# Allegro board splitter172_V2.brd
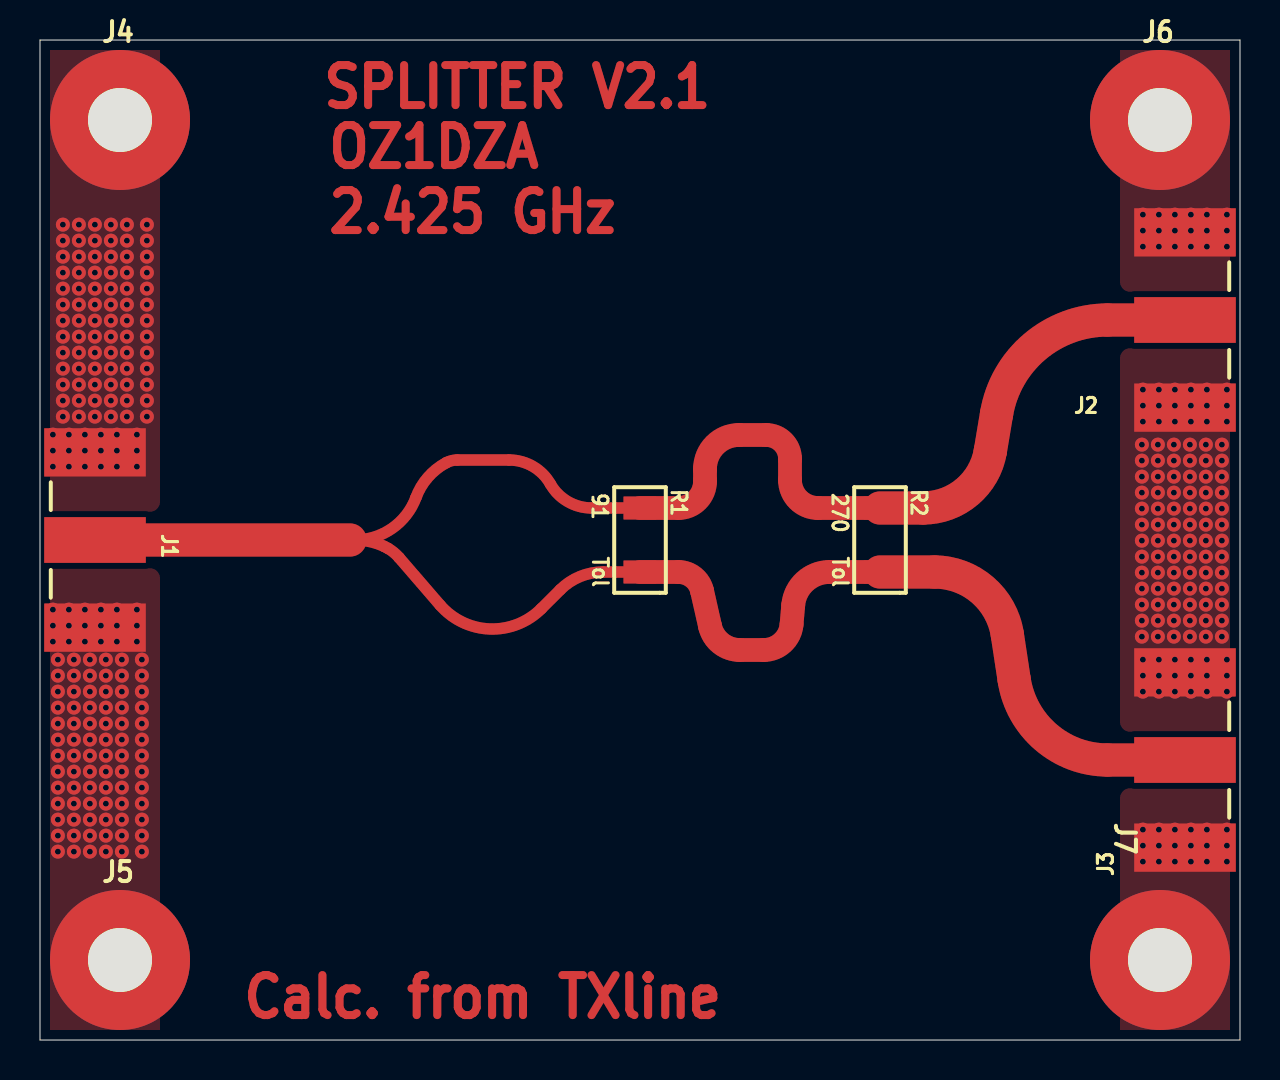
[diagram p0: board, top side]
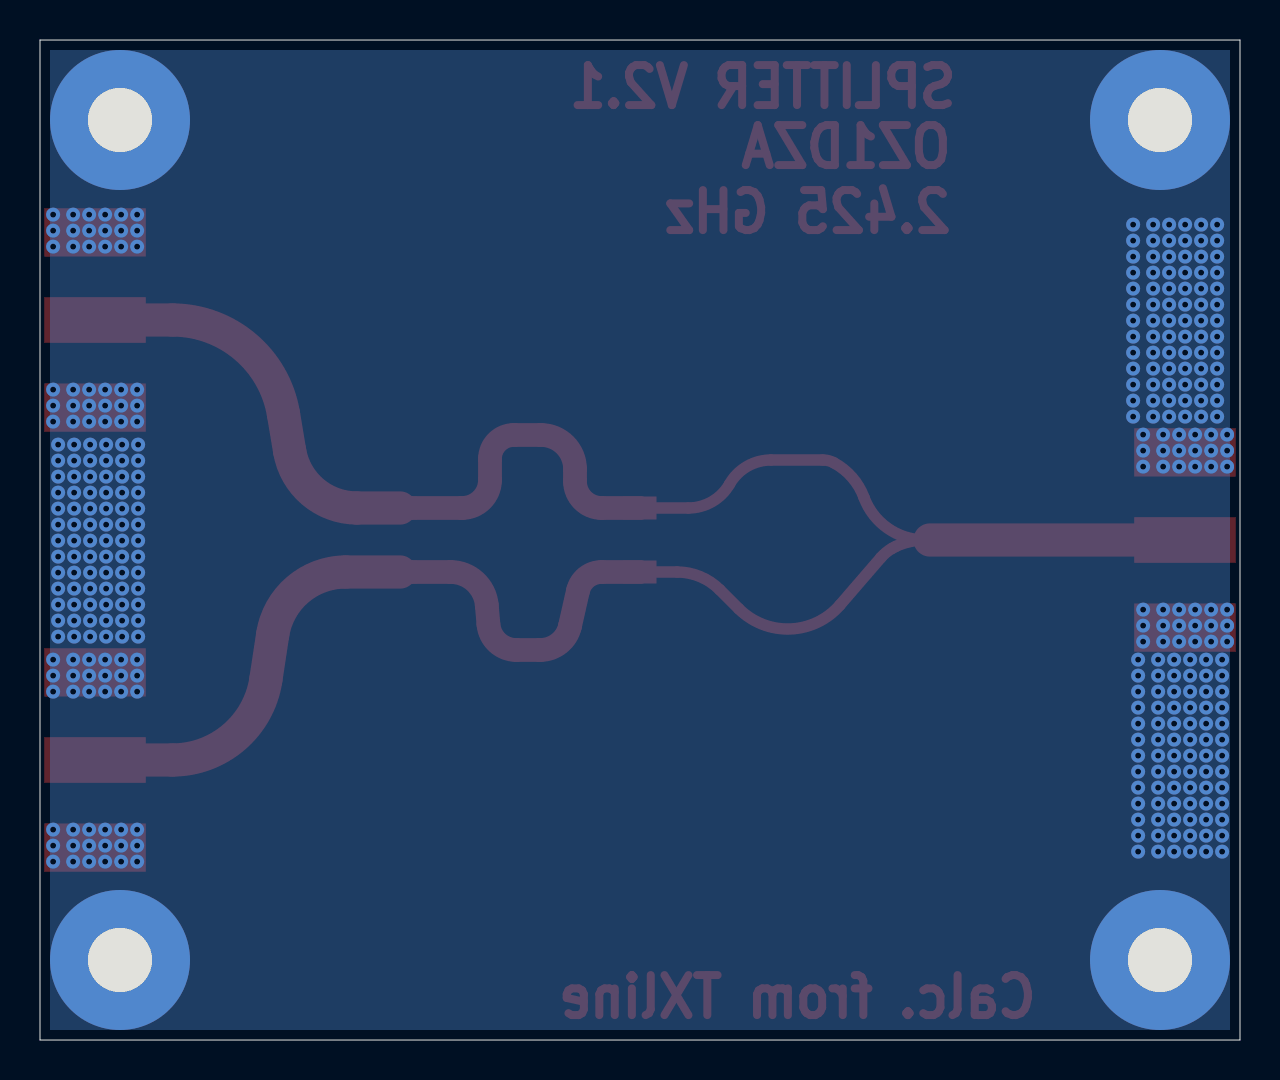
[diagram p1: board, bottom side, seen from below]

Outline 60 x 50 mm; copper layers: TOP, BOTTOM. Coordinates in mm from the lower left corner of the outline.
Outline path: 0,50 0,0 60,0 60,50 0,50

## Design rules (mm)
constraint set DEFAULT: min track width 0.3

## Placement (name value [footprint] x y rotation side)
J1  142-0701-801  [142-0701-851]  6.94 22.81 270 top
J2  142-0701-801  [142-0701-851]  53.06 38.19 90 top
J3  142-0701-801  [142-0701-851]  53.06 16.19 90 top
J4  -  [CON_C700H320]  4 46 0 top
J5  -  [CON_C700H320]  4 4 0 top
J6  -  [CON_C700H320]  56 46 0 top
J7  -  [CON_C700H320]  56 4 0 top
NOREF  -  []  0 50 0 top
NOREF#2  -  []  0 50 0 top
NOREF#3  -  []  60 0 90 top
R1  91  [R1206]  30 25 270 top
R2  270  [R1206]  42 25 270 top

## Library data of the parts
J1-J3 = 142-0701-801
J4-J7 = CON1
R1 = RC0603FR-0791RL: Tolerance: Tol
R2 = RMCF0603FT270R: Tolerance: Tol

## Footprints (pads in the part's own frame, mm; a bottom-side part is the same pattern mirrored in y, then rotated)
142-0701-851
  rect 2.413x5.08 smd: 1(-6.572,-4.19) 3(2.191,-4.19)
  rect 2.286x5.08 smd: 2(-2.191,-4.19)
CON_C700H320
  round 7 hole 3.2: 1(0,0)
R1206
  rect 1.15x1.65 smd: 1(-1.6,0) 2(1.6,0)

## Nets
GND: J1.1 J1.3 J2.1 J2.3 J3.1 J3.3 J4.1 J5.1 J6.1 J7.1
SIG: J1.2 J2.2 J3.2 R1.1 R1.2 R2.1 R2.2

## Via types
v1: diameter 0.7, hole 0.3, TOP to BOTTOM, 342 vias

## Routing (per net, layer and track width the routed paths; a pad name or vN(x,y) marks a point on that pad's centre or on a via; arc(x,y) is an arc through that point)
GND:
  vias: v1(0.64,30.27) v1(0.64,29.47) v1(0.64,28.67) v1(0.64,21.52) v1(0.64,20.72) v1(0.64,19.92) v1(0.89,19.02) v1(0.89,18.22) v1(0.89,17.42) v1(0.89,16.62) v1(0.89,15.82) v1(0.89,15.02) v1(0.89,14.22) v1(0.89,13.42) v1(0.89,12.62) v1(0.89,11.82) v1(0.89,11.02) v1(0.89,10.22) v1(0.89,9.42) v1(1.14,40.77) v1(1.14,39.97) v1(1.14,39.17) v1(1.14,38.37) v1(1.14,37.57) v1(1.14,36.77) v1(1.14,35.97) v1(1.14,35.17) v1(1.14,34.37) v1(1.14,33.57) v1(1.14,32.77) v1(1.14,31.97) v1(1.14,31.17) v1(1.44,30.27) v1(1.44,29.47) v1(1.44,28.67) v1(1.44,21.52) v1(1.44,20.72) v1(1.44,19.92) v1(1.69,19.02) v1(1.69,18.22) v1(1.69,17.42) v1(1.69,16.62) v1(1.69,15.82) v1(1.69,15.02) v1(1.69,14.22) v1(1.69,13.42) v1(1.69,12.62) v1(1.69,11.82) v1(1.69,11.02) v1(1.69,10.22) v1(1.69,9.42) v1(1.94,40.77) v1(1.94,39.97) v1(1.94,39.17) v1(1.94,38.37) v1(1.94,37.57) v1(1.94,36.77) v1(1.94,35.97) v1(1.94,35.17) v1(1.94,34.37) v1(1.94,33.57) v1(1.94,32.77) v1(1.94,31.97) v1(1.94,31.17) v1(2.24,30.27) v1(2.24,29.47) v1(2.24,28.67) v1(2.24,21.52) v1(2.24,20.72) v1(2.24,19.92) v1(2.49,19.02) v1(2.49,18.22) v1(2.49,17.42) v1(2.49,16.62) v1(2.49,15.82) v1(2.49,15.02) v1(2.49,14.22) v1(2.49,13.42) v1(2.49,12.62) v1(2.49,11.82) v1(2.49,11.02) v1(2.49,10.22) v1(2.49,9.42) v1(2.74,40.77) v1(2.74,39.97) v1(2.74,39.17) v1(2.74,38.37) v1(2.74,37.57) v1(2.74,36.77) v1(2.74,35.97) v1(2.74,35.17) v1(2.74,34.37) v1(2.74,33.57) v1(2.74,32.77) v1(2.74,31.97) v1(2.74,31.17) v1(3.04,30.27) v1(3.04,29.47) v1(3.04,28.67) v1(3.04,21.52) v1(3.04,20.72) v1(3.04,19.92) v1(3.29,19.02) v1(3.29,18.22) v1(3.29,17.42) v1(3.29,16.62) v1(3.29,15.82) v1(3.29,15.02) v1(3.29,14.22) v1(3.29,13.42) v1(3.29,12.62) v1(3.29,11.82) v1(3.29,11.02) v1(3.29,10.22) v1(3.29,9.42) v1(3.54,40.77) v1(3.54,39.97) v1(3.54,39.17) v1(3.54,38.37) v1(3.54,37.57) v1(3.54,36.77) v1(3.54,35.97) v1(3.54,35.17) v1(3.54,34.37) v1(3.54,33.57) v1(3.54,32.77) v1(3.54,31.97) v1(3.54,31.17) v1(3.84,30.27) v1(3.84,29.47) v1(3.84,28.67) v1(3.84,21.52) v1(3.84,20.72) v1(3.84,19.92) v1(4.09,19.02) v1(4.09,18.22) v1(4.09,17.42) v1(4.09,16.62) v1(4.09,15.82) v1(4.09,15.02) v1(4.09,14.22) v1(4.09,13.42) v1(4.09,12.62) v1(4.09,11.82) v1(4.09,11.02) v1(4.09,10.22) v1(4.09,9.42) v1(4.34,40.77) v1(4.34,39.97) v1(4.34,39.17) v1(4.34,38.37) v1(4.34,37.57) v1(4.34,36.77) v1(4.34,35.97) v1(4.34,35.17) v1(4.34,34.37) v1(4.34,33.57) v1(4.34,32.77) v1(4.34,31.97) v1(4.34,31.17) v1(4.84,30.27) v1(4.84,29.47) v1(4.84,28.67) v1(4.84,21.52) v1(4.84,20.72) v1(4.84,19.92) v1(5.09,19.02) v1(5.09,18.22) v1(5.09,17.42) v1(5.09,16.62) v1(5.09,15.82) v1(5.09,15.02) v1(5.09,14.22) v1(5.09,13.42) v1(5.09,12.62) v1(5.09,11.82) v1(5.09,11.02) v1(5.09,10.22) v1(5.09,9.42) v1(5.34,40.77) v1(5.34,39.97) v1(5.34,39.17) v1(5.34,38.37) v1(5.34,37.57) v1(5.34,36.77) v1(5.34,35.97) v1(5.34,35.17) v1(5.34,34.37) v1(5.34,33.57) v1(5.34,32.77) v1(5.34,31.97) v1(5.34,31.17) v1(55.14,41.27) v1(55.14,40.47) v1(55.14,39.67) v1(55.14,32.52) v1(55.14,31.72) v1(55.14,30.92) v1(55.09,29.77) v1(55.09,28.97) v1(55.09,28.17) v1(55.09,27.37) v1(55.09,26.57) v1(55.09,25.77) v1(55.09,24.97) v1(55.09,24.17) v1(55.09,23.37) v1(55.09,22.57) v1(55.09,21.77) v1(55.09,20.97) v1(55.09,20.17) v1(55.14,19.02) v1(55.14,18.22) v1(55.14,17.42) v1(55.14,10.52) v1(55.14,9.72) v1(55.14,8.92) v1(55.94,41.27) v1(55.94,40.47) v1(55.94,39.67) v1(55.94,32.52) v1(55.94,31.72) v1(55.94,30.92) v1(55.89,29.77) v1(55.89,28.97) v1(55.89,28.17) v1(55.89,27.37) v1(55.89,26.57) v1(55.89,25.77) v1(55.89,24.97) v1(55.89,24.17) v1(55.89,23.37) v1(55.89,22.57) v1(55.89,21.77) v1(55.89,20.97) v1(55.89,20.17) v1(55.94,19.02) v1(55.94,18.22) v1(55.94,17.42) v1(55.94,10.52) v1(55.94,9.72) v1(55.94,8.92) v1(56.74,41.27) v1(56.74,40.47) v1(56.74,39.67) v1(56.74,32.52) v1(56.74,31.72) v1(56.74,30.92) v1(56.69,29.77) v1(56.69,28.97) v1(56.69,28.17) v1(56.69,27.37) v1(56.69,26.57) v1(56.69,25.77) v1(56.69,24.97) v1(56.69,24.17) v1(56.69,23.37) v1(56.69,22.57) v1(56.69,21.77) v1(56.69,20.97) v1(56.69,20.17) v1(56.74,19.02) v1(56.74,18.22) v1(56.74,17.42) v1(56.74,10.52) v1(56.74,9.72) v1(56.74,8.92) v1(57.54,41.27) v1(57.54,40.47) v1(57.54,39.67) v1(57.54,32.52) v1(57.54,31.72) v1(57.54,30.92) v1(57.49,29.77) v1(57.49,28.97) v1(57.49,28.17) v1(57.49,27.37) v1(57.49,26.57) v1(57.49,25.77) v1(57.49,24.97) v1(57.49,24.17) v1(57.49,23.37) v1(57.49,22.57) v1(57.49,21.77) v1(57.49,20.97) v1(57.49,20.17) v1(57.54,19.02) v1(57.54,18.22) v1(57.54,17.42) v1(57.54,10.52) v1(57.54,9.72) v1(57.54,8.92) v1(58.34,41.27) v1(58.34,40.47) v1(58.34,39.67) v1(58.34,32.52) v1(58.34,31.72) v1(58.34,30.92) v1(58.29,29.77) v1(58.29,28.97) v1(58.29,28.17) v1(58.29,27.37) v1(58.29,26.57) v1(58.29,25.77) v1(58.29,24.97) v1(58.29,24.17) v1(58.29,23.37) v1(58.29,22.57) v1(58.29,21.77) v1(58.29,20.97) v1(58.29,20.17) v1(58.34,19.02) v1(58.34,18.22) v1(58.34,17.42) v1(58.34,10.52) v1(58.34,9.72) v1(58.34,8.92) v1(59.09,29.77) v1(59.09,28.97) v1(59.09,28.17) v1(59.09,27.37) v1(59.09,26.57) v1(59.09,25.77) v1(59.09,24.97) v1(59.09,24.17) v1(59.09,23.37) v1(59.09,22.57) v1(59.09,21.77) v1(59.09,20.97) v1(59.09,20.17) v1(59.34,41.27) v1(59.34,40.47) v1(59.34,39.67) v1(59.34,32.52) v1(59.34,31.72) v1(59.34,30.92) v1(59.34,19.02) v1(59.34,18.22) v1(59.34,17.42) v1(59.34,10.52) v1(59.34,9.72) v1(59.34,8.92)
SIG: length 121.9
  TOP w0.571: R1.2 28.15,23.4 arc(26.99,23.17) 26.02,22.52 25.06,21.56 arc(22.49,20.55) 20,21.75 17.95,24.12 arc(17.69,24.37) 17.4,24.58 arc(17.3,24.63) 17.21,24.68 arc(16.5,24.92) 15.75,25 ; 15.75,25 15.5,25 ; 15.75,25 arc(17.61,25.58) 18.8,27.12 arc(19.39,28.13) 20.3,28.86 arc(20.57,28.96) 20.86,29 23.46,29 arc(24.65,28.68) 25.52,27.8 arc(26.39,26.92) 27.58,26.6 R1.1
  TOP w1.19: R2.1 38.9,26.6 arc(37.91,27.01) 37.5,28 37.5,29.06 arc(37.15,29.9) 36.31,30.25 34.95,30.25 arc(33.75,29.75) 33.25,28.55 33.25,27.93 arc(32.86,26.99) 31.92,26.6 R1.1 ; R1.2 31.92,23.4 arc(32.68,23.13) 33.1,22.45 33.5,20.69 arc(34.04,19.83) 34.99,19.5 36.18,19.5 arc(37.13,19.87) 37.58,20.78 37.66,21.74 arc(38.24,22.92) 39.47,23.4 R2.2
  TOP w1.663: R2.2 44.72,23.4 arc(47.12,22.51) 48.37,20.27 48.71,18.01 arc(50.3,15.14) 53.38,14 J3.2 ; R2.1 44.16,26.6 arc(46.36,27.41) 47.52,29.44 47.83,31.3 arc(49.74,34.67) 53.38,36 J2.2 ; J1.2 15.5,25

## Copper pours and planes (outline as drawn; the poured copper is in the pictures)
GND on TOP: 54,50 54,0 60,0 60,50
GND on TOP: 0,50 0,0 6,0 6,50
GND on BOTTOM: 0.5,49.5 0.5,0.5 60,0.5 60,49.5

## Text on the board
TOP: Calc. from TXline | SPLITTER V2.1 | OZ1DZA | 2.425 GHz
